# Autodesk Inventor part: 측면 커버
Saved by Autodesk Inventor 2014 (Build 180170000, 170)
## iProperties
Created: 2026-01
Part Number: 측면 커버
Material: 일반
Document SubType Name: Modeling
Designer: dg
Density: 1 g/cm^3
Appearance: 기본값
Author: dg
Author: jhkim
Creation Date: 2026-01-09
Sending System: Autodesk Inventor 2026
Preprocessor: ST-DEVELOPER v20.1
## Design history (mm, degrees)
node "측면 커버1"
node "솔리드1"
node "기준1"
